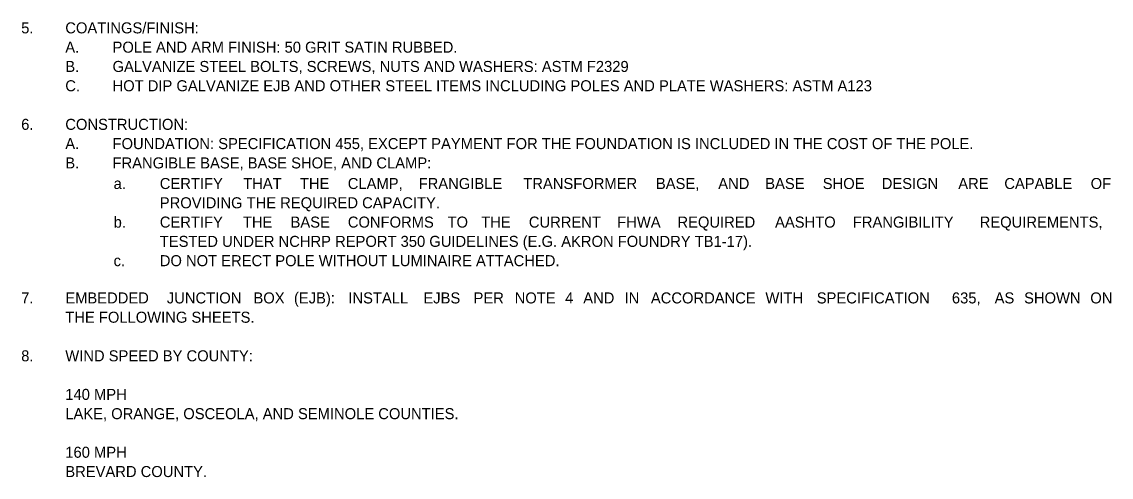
# Model space of a CAD drawing. Extents: x 3132 to 3864, y -21 to 491.
# Drawn here: x 3504 to 3849.9, y 319.4 to 464.1 of the extents above; entities that cross this region are included whole.
import ezdxf

# ---------------------------------------------------------------- set-up
doc = ezdxf.new("R2010")
doc.units = 0
doc.layers.add('TextNotes', color=7, linetype='Continuous')

msp = doc.modelspace()

# ---------------------------------------------------------------- texts
at = {"layer": 'TextNotes'}
for s, p in [('5.', (3503.85, 460.37)), ('COATINGS/FINISH: ', (3517.85, 460.37)), ('A.', (3517.85, 454.24)), ('POLE AND ARM FINISH: 50 GRIT SATIN RUBBED.', (3532.85, 454.24)), ('B.', (3517.85, 448.12)), ('GALVANIZE STEEL BOLTS, SCREWS, NUTS AND WASHERS: ASTM F2329', (3532.85, 448.12)), ('C.', (3517.85, 441.99)), ('HOT DIP GALVANIZE EJB AND OTHER STEEL ITEMS INCLUDING POLES AND PLATE WASHERS: ASTM A123', (3532.85, 441.99)), ('6.', (3503.85, 429.74)), ('CONSTRUCTION:', (3517.85, 429.74)), ('A.', (3517.85, 423.62)), ('FOUNDATION: SPECIFICATION 455, EXCEPT PAYMENT FOR THE FOUNDATION IS INCLUDED IN THE COST OF THE POLE.', (3532.85, 423.62)), ('B.', (3517.85, 417.49)), ('FRANGIBLE BASE, BASE SHOE, AND CLAMP:', (3532.85, 417.49)), ('a.', (3533.19, 410.95)), ('CERTIFY ', (3547.85, 410.95)), ('THAT ', (3574.32, 410.95)), ('THE ', (3592.34, 410.95)), ('CLAMP, ', (3607.53, 410.95)), ('FRANGIBLE ', (3630.02, 410.95)), ('TRANSFORMER ', (3663.25, 410.95)), ('BASE, ', (3705.34, 410.95)), ('AND ', (3725.13, 410.95)), ('BASE ', (3740.05, 410.95)), ('SHOE ', (3758.31, 410.95)), ('DESIGN ', (3777.04, 410.95)), ('ARE ', (3801.33, 410.95)), ('CAPABLE ', (3815.95, 410.95)), ('OF ', (3843.36, 410.95)), ('PROVIDING THE REQUIRED CAPACITY. ', (3547.85, 404.83)), ('b.', (3533.19, 398.7)), ('CERTIFY ', (3547.85, 398.7)), ('THE ', (3574.24, 398.7)), ('BASE ', (3589.36, 398.7)), ('CONFORMS ', (3607.54, 398.7)), ('TO ', (3639.19, 398.7)), ('THE ', (3649.89, 398.7)), ('CURRENT ', (3665.01, 398.7)), ('FHWA ', (3693.07, 398.7)), ('REQUIRED ', (3712.18, 398.7)), ('AASHTO ', (3743.17, 398.7)), ('FRANGIBILITY ', (3767.86, 398.7)), ('REQUIREMENTS, ', (3808.13, 398.7)), ('TESTED UNDER NCHRP REPORT 350 GUIDELINES (E.G. AKRON FOUNDRY TB1-17).', (3547.85, 392.58)), ('c.', (3533.19, 386.45)), ('DO NOT ERECT POLE WITHOUT LUMINAIRE ATTACHED.', (3547.85, 386.45)), ('7.', (3503.85, 374.62)), ('EMBEDDED ', (3517.85, 374.62)), ('JUNCTION ', (3550.09, 374.62)), ('BOX ', (3577.59, 374.62)), ('(EJB): ', (3590.44, 374.62)), ('INSTALL ', (3607.7, 374.62)), ('EJBS ', (3631.53, 374.62)), ('PER ', (3647.46, 374.62)), ('NOTE ', (3660.51, 374.62)), ('4 ', (3676.53, 374.62)), ('AND ', (3682.28, 374.62)), ('IN ', (3695.41, 374.62)), ('ACCORDANCE ', (3703.75, 374.62)), ('WITH ', (3740.12, 374.62)), ('SPECIFICATION ', (3756.4, 374.62)), ('635, ', (3799.31, 374.62)), ('AS ', (3812.88, 374.62)), ('SHOWN ', (3822.23, 374.62)), ('ON ', (3843.25, 374.62)), ('THE FOLLOWING SHEETS. ', (3517.85, 368.49)), ('8.', (3503.85, 356.24)), ('WIND SPEED BY COUNTY:', (3517.85, 356.24)), ('140 MPH', (3517.85, 343.99)), ('LAKE, ORANGE, OSCEOLA, AND SEMINOLE COUNTIES.', (3517.85, 337.87)), ('160 MPH', (3517.85, 325.62)), ('BREVARD COUNTY.', (3517.85, 319.49))]:
    msp.add_text(s, height=3.5, dxfattribs=at).set_placement(p)

doc.saveas('drawing.dxf')
